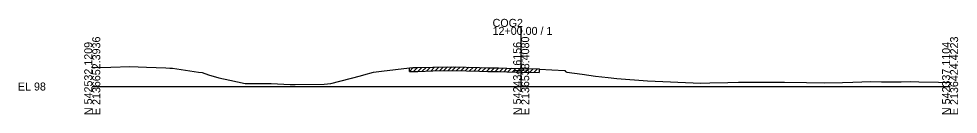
# Model space of a CAD drawing. Extents: x -13397 to 2303, y -10 to 39059.
# Drawn here: x -25.7 to 302.8, y 3990.3 to 4023.7 of the extents above; entities that cross this region are included whole.
import ezdxf

# ---------------------------------------------------------------- set-up
doc = ezdxf.new("R2010")
doc.units = 0
for name, color, linetype in [('RD_GPK_XS_Cell', 7, 'Continuous'), ('RD_XS_ExGround', 7, 'Continuous'), ('RD_XS_ExPaveRet', 7, 'Continuous'), ('RD_XS_TX_Elev_EX', 7, 'Continuous')]:
    doc.layers.add(name, color=color, linetype=linetype)

msp = doc.modelspace()

# ---------------------------------------------------------------- linework, layer by layer
at = {"layer": 'RD_GPK_XS_Cell'}
for p, q in [((150, 4000), (150, 4020.86)), ((0, 4000), (150, 4000)), ((150, 4000), (300, 4000))]:
    msp.add_line(p, q, dxfattribs=at)
at = {"layer": 'RD_XS_ExGround'}
for p, q in [((0, 4006.64), (1.03, 4006.68)), ((1.03, 4006.68), (6.55, 4006.8)), ((6.55, 4006.8), (13.1, 4006.95)), ((13.1, 4006.95), (18.98, 4006.73)), ((18.98, 4006.73), (25.71, 4006.5)), ((25.71, 4006.5), (27.15, 4006.45)), ((27.15, 4006.45), (28.08, 4006.41)), ((28.08, 4006.41), (37.1, 4005.05)), ((37.1, 4005.05), (38.39, 4004.87)), ((38.39, 4004.87), (40.71, 4004.13)), ((95, 4004.05), (98.36, 4005.05)), ((98.36, 4005.05), (101.13, 4005.4)), ((101.13, 4005.4), (110.89, 4006.57)), ((110.89, 4006.57), (112.07, 4006.6)), ((112.07, 4006.6), (113.83, 4006.61)), ((113.83, 4006.61), (119.11, 4006.73)), ((119.11, 4006.73), (126.24, 4006.88)), ((126.24, 4006.88), (135.37, 4006.65)), ((135.37, 4006.65), (138.29, 4006.56)), ((138.29, 4006.56), (138.76, 4006.55)), ((138.76, 4006.55), (142.07, 4006.5)), ((142.07, 4006.5), (144.95, 4006.42)), ((144.95, 4006.42), (150, 4006.3)), ((150, 4006.3), (156.25, 4006.15)), ((156.25, 4006.15), (156.42, 4006.02)), ((156.42, 4006.02), (160.67, 4005.79)), ((160.67, 4005.79), (165.26, 4005.56)), ((165.26, 4005.56), (165.5, 4005.21)), ((165.5, 4005.21), (165.97, 4005.01)), ((165.97, 4005.01), (171.37, 4004.27)), ((40.71, 4004.13), (44.25, 4003.04)), ((44.25, 4003.04), (48.15, 4002.18)), ((48.15, 4002.18), (53.48, 4001.06)), ((83.41, 4001.06), (93.79, 4003.74)), ((93.79, 4003.74), (95, 4004.05)), ((171.37, 4004.27), (175.97, 4003.59)), ((175.97, 4003.59), (180.47, 4003.19)), ((180.47, 4003.19), (183.5, 4002.84)), ((183.5, 4002.84), (194.23, 4001.96)), ((194.23, 4001.96), (212.84, 4001.15)), ((265.98, 4001.48), (272.34, 4001.75)), ((272.34, 4001.75), (275.98, 4001.68)), ((275.98, 4001.68), (282.9, 4001.61)), ((282.9, 4001.61), (285.98, 4001.71)), ((285.98, 4001.71), (289.06, 4001.68)), ((289.06, 4001.68), (295.98, 4001.49)), ((53.48, 4001.06), (54.03, 4001.06)), ((54.03, 4001.06), (62.53, 4001.04)), ((62.53, 4001.04), (69.26, 4000.71)), ((69.26, 4000.71), (70.91, 4000.73)), ((70.91, 4000.73), (81.05, 4000.83)), ((81.05, 4000.83), (83.41, 4001.06)), ((212.84, 4001.15), (215.97, 4001.33)), ((215.97, 4001.33), (222.33, 4001.46)), ((222.33, 4001.46), (225.97, 4001.53)), ((225.97, 4001.53), (229.62, 4001.51)), ((229.62, 4001.51), (242.13, 4001.5)), ((242.13, 4001.5), (249.76, 4001.45)), ((249.76, 4001.45), (255.97, 4001.32)), ((255.97, 4001.32), (262.43, 4001.38)), ((262.43, 4001.38), (265.98, 4001.48)), ((295.98, 4001.49), (300, 4001.46))]:
    msp.add_line(p, q, dxfattribs=at)
at = {"layer": 'RD_XS_ExPaveRet'}
for p, q in [((110.89, 4005.27), (112.22, 4006.6)), ((110.89, 4005.27), (110.89, 4006.57)), ((110.89, 4005.27), (112.07, 4005.3)), ((112.07, 4005.3), (113.83, 4005.31)), ((112.39, 4005.3), (113.69, 4006.61)), ((113.83, 4005.31), (119.11, 4005.43)), ((113.89, 4005.31), (115.22, 4006.64)), ((115.39, 4005.34), (116.72, 4006.67)), ((116.89, 4005.38), (118.22, 4006.71)), ((118.39, 4005.41), (119.72, 4006.74)), ((119.11, 4005.43), (126.24, 4005.58)), ((119.89, 4005.44), (121.22, 4006.77)), ((121.39, 4005.47), (122.72, 4006.8)), ((122.89, 4005.51), (124.22, 4006.84)), ((124.39, 4005.54), (125.72, 4006.87)), ((125.89, 4005.57), (127.17, 4006.86)), ((126.24, 4005.58), (135.37, 4005.35)), ((127.39, 4005.55), (128.66, 4006.82)), ((128.89, 4005.51), (130.16, 4006.78)), ((130.39, 4005.47), (131.66, 4006.74)), ((131.89, 4005.44), (133.16, 4006.71)), ((133.39, 4005.4), (134.66, 4006.67)), ((134.89, 4005.36), (136.15, 4006.63)), ((135.37, 4005.35), (138.29, 4005.26)), ((136.39, 4005.32), (137.65, 4006.58)), ((137.89, 4005.27), (139.16, 4006.54)), ((138.29, 4005.26), (138.76, 4005.25)), ((138.76, 4005.25), (142.07, 4005.2)), ((139.39, 4005.24), (140.67, 4006.52)), ((140.89, 4005.22), (142.17, 4006.49)), ((142.07, 4005.2), (144.95, 4005.12)), ((142.39, 4005.19), (143.65, 4006.45)), ((143.89, 4005.15), (145.15, 4006.41)), ((144.95, 4005.12), (150, 4005)), ((145.39, 4005.11), (146.66, 4006.38)), ((146.89, 4005.07), (148.16, 4006.34)), ((148.39, 4005.03), (149.66, 4006.3)), ((149.89, 4005), (151.16, 4006.27)), ((150, 4005), (156.25, 4004.85)), ((151.39, 4004.96), (152.66, 4006.23)), ((152.89, 4004.93), (154.16, 4006.2)), ((154.39, 4004.89), (155.66, 4006.16)), ((156.25, 4006.15), (156.25, 4004.85))]:
    msp.add_line(p, q, dxfattribs=at)

# ---------------------------------------------------------------- texts
at = {"layer": 'RD_GPK_XS_Cell'}
for s, p in [('COG2', (140, 4020.86)), ('12+00.00 / 1', (140, 4018.06)), ('EL 98', (-26, 3998.6))]:
    msp.add_text(s, height=2.8, dxfattribs=at).set_placement(p)
for s, p in [('N 542532.1209', (0, 3990)), ('E 2136652.3936', (2.8, 3990)), ('N 542434.6156', (150, 3990)), ('E 2136538.4080', (152.8, 3990)), ('N 542337.1104', (300, 3990)), ('E 2136424.4223', (302.8, 3990))]:
    msp.add_text(s, height=2.8, rotation=90, dxfattribs=at).set_placement(p)
at = {"layer": 'RD_XS_TX_Elev_EX'}
msp.add_text('104.30', height=1, rotation=90, dxfattribs=at).set_placement((150.75, 4007.3))

doc.saveas('drawing.dxf')
